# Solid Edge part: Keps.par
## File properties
Author: KULL
Template: Iso Metric Part.par
Last saved by: KULL
Revision: 11
Application: Solid Edge
Accuracy: 0,990
Face Style: Model Default
Fill Style: Normal
Coef. of Thermal Exp: 0.0
Thermal Conductivity: 0.0
Specific Heat: 0.0
Modulus of Elasticity: 0.0
Poisson's Ratio: 0.0
Yield Stress: 0.0
Ultimate Stress: 0.0
Elongation: 0.0
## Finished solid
Body 1: solid body, 75 faces, 170 edges, 96 vertices.
  Faces by surface: cylinder 37, torus 24, plane 14
  Edges by curve: circle 106, line 64
Bounding box of the edges (mm; curved faces can reach further): 4.000 x 24.285 x 27.407, from (-38, -24.427, 39.7922) to (-34, -0.1423, 67.1996).
Cylindrical faces by radius (mm): R0.2 x12, R0.4 x4, R1 x6, R1.0001 x2, R1.5 x1, R2 x8, R3 x1, R5 x2, R10 x1
Toroidal faces (ring radius, tube radius in mm): R0.8 r0.2 x4, R0.8001 r0.2 x2, R1.2 r0.2 x4, R1.2001 r0.2 x2, R1.4 r0.4 x4, R2.4 r0.4 x4, R2.6 r0.4 x2, R4.6 r0.4 x2
Planar faces by outward normal: +x 3, -x 3, oblique 8
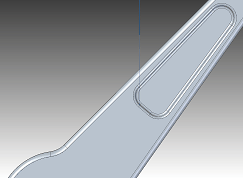
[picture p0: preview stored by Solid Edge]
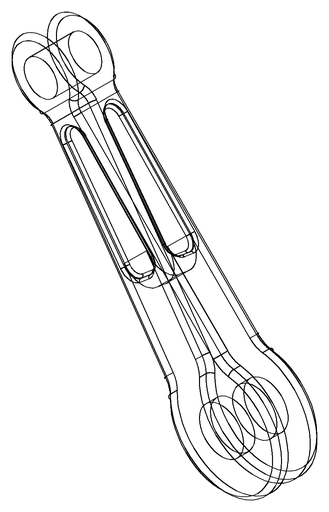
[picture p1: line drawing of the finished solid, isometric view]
